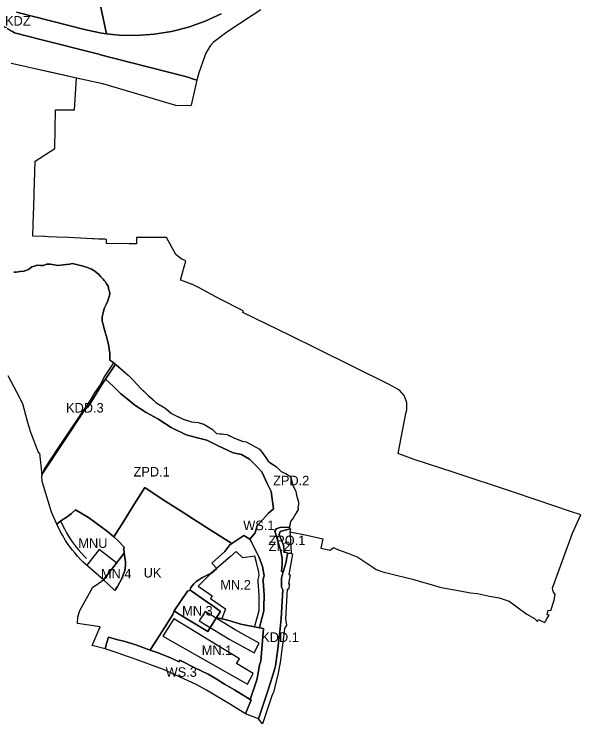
# Model space of a CAD drawing. Extents: x 7422965 to 7424741, y 5551047 to 5553849.
# Drawn here: x 7424029 to 7424741, y 5551047 to 5551939 of the extents above; entities that cross this region are included whole.
import ezdxf

# ---------------------------------------------------------------- set-up
doc = ezdxf.new("R2010")
doc.units = 0
for name, color, linetype in [('LIN_Linia Zabudowy Nieprzekraczalna', 7, 'Continuous'), ('linie_rozgraniczajace', 7, 'Continuous'), ('oznaczenia_przeznaczen', 7, 'Continuous'), ('Tereny dla których obowiązuje MPZP LInia tramwajowa_', 7, 'Continuous'), ('Tereny dla których obowiązuje MPZP_SIEWNA_', 7, 'Continuous')]:
    doc.layers.add(name, color=color, linetype=linetype)

msp = doc.modelspace()

# ---------------------------------------------------------------- linework, layer by layer
at = {"layer": 'LIN_Linia Zabudowy Nieprzekraczalna'}
for points in [[(7424086.9, 5551302.23), (7424091.81, 5551292.33), (7424094.5, 5551287.54), (7424098.23, 5551281.11), (7424101.45, 5551276.33), (7424102.69, 5551274.63), (7424106.51, 5551269.64), (7424109.66, 5551265.92), (7424112.87, 5551262.27), (7424116.93, 5551257.71), (7424119.41, 5551255.39)], [(7424157.46, 5551249.4), (7424135.64, 5551266.43), (7424120.13, 5551246.75)], [(7424330.98, 5551169.62), (7424331.53, 5551171.74), (7424336.3, 5551190.07), (7424336.37, 5551194.34), (7424336.6, 5551209.2), (7424335.4, 5551226.04), (7424335.03, 5551228.64), (7424336.65, 5551233.69), (7424335.86, 5551237.95), (7424335.86, 5551237.95), (7424332.94, 5551250.04), (7424331.02, 5551258.06), (7424316.07, 5551256.25), (7424307.51, 5551264.16), (7424300.57, 5551257.64), (7424276.18, 5551236.6), (7424259.68, 5551220.57), (7424273.33, 5551211.16), (7424277.51, 5551208.28), (7424275.25, 5551204.98), (7424294.21, 5551191.91), (7424289.71, 5551179.29)], [(7424261.26, 5551176.82), (7424299.42, 5551153.27), (7424330.27, 5551136.45), (7424336.49, 5551149.01), (7424306.45, 5551165.38), (7424268.81, 5551188.62), (7424261.26, 5551176.82)], [(7424229.09, 5551179.23), (7424221.21, 5551166.77), (7424215.27, 5551157.4), (7424321.63, 5551097.36), (7424329.04, 5551110.48), (7424308.15, 5551123.21), (7424311.69, 5551129.27), (7424229.09, 5551179.23)]]:
    msp.add_lwpolyline(points, dxfattribs=at)
at = {"layer": 'linie_rozgraniczajace'}
for points in [[(7424120.1, 5552030.52), (7424144.75, 5551914.84), (7424138.51, 5551915.55), (7424134.69, 5551916.34), (7424116.88, 5551920.02), (7424031.65, 5551941.72)], [(7424288.66, 5551939.77), (7424268.6, 5551930.5), (7424247.79, 5551923.1), (7424226.39, 5551917.62), (7424204.58, 5551914.1), (7424182.55, 5551912.57), (7424160.46, 5551913.06), (7424144.75, 5551914.84), (7424120.1, 5552030.52)], [(7424338.43, 5551944.9), (7424327.49, 5551937.52), (7424295.81, 5551916.92), (7424278.65, 5551903.92), (7424275.17, 5551900.11), (7424272.19, 5551895.33), (7424269.35, 5551890.42), (7424267.75, 5551885.84), (7424260.49, 5551865.76), (7424258.29, 5551856.52), (7424253.82, 5551857.89), (7424248.24, 5551859.6), (7424244.12, 5551860.87), (7424153.41, 5551884.24), (7424137.07, 5551888.39), (7424134.98, 5551888.92), (7424060.02, 5551907.95), (7424029.29, 5551915.75), (7424026.49, 5551917.43), (7424025.86, 5551917.8), (7424023.81, 5551919.03), (7424016.3, 5551923.51), (7424014.01, 5551923.99), (7423937.85, 5551940.09)], [(7424031.65, 5551941.72), (7424116.88, 5551920.02), (7424134.69, 5551916.34), (7424138.51, 5551915.55), (7424144.75, 5551914.84), (7424160.46, 5551913.06), (7424182.55, 5551912.57), (7424204.58, 5551914.1), (7424226.39, 5551917.62), (7424247.79, 5551923.1), (7424268.6, 5551930.5), (7424288.66, 5551939.77)], [(7424026.49, 5551917.43), (7424029.29, 5551915.75), (7424060.02, 5551907.95), (7424134.98, 5551888.92), (7424137.07, 5551888.39), (7424153.41, 5551884.24), (7424244.12, 5551860.87), (7424248.24, 5551859.6), (7424253.82, 5551857.89), (7424258.29, 5551856.52), (7424251.03, 5551825.07), (7424250.65, 5551824.29), (7424231.82, 5551824.48), (7424207.95, 5551831.54), (7424195.27, 5551835.29), (7424139.86, 5551851.68), (7424106.89, 5551859.08), (7424053.04, 5551871.18), (7424030.65, 5551876.21), (7424024.75, 5551877.53)], [(7424143.23, 5551480.6), (7424155.85, 5551499.51), (7424157.31, 5551498.25), (7424171.99, 5551485.61), (7424177.75, 5551479.64), (7424187.73, 5551468.97), (7424196.98, 5551460.22), (7424206.73, 5551451.46), (7424217.86, 5551444.5), (7424226.44, 5551437.58), (7424240.98, 5551430.18), (7424251.49, 5551427.06), (7424260, 5551426.11), (7424266.96, 5551424.11), (7424277.5, 5551417.67), (7424283.07, 5551412.39), (7424295.73, 5551411.05), (7424305.5, 5551406.56), (7424314.91, 5551402.72), (7424320.18, 5551401.96), (7424337.02, 5551392.72), (7424341.56, 5551386.77), (7424347.82, 5551377.72), (7424358.13, 5551370.24), (7424364.03, 5551364.43), (7424370.78, 5551361.67), (7424374.13, 5551359.25), (7424376.35, 5551356.96), (7424378.82, 5551347.56), (7424382.34, 5551339.53), (7424383.41, 5551334.98), (7424385.78, 5551325.96), (7424385.87, 5551323.15), (7424384.98, 5551319.4), (7424385.56, 5551316.43), (7424382.32, 5551311.88), (7424379.31, 5551306.11), (7424375.8, 5551301.77), (7424374.36, 5551294.1), (7424363.6, 5551294.44), (7424357.85, 5551292.65), (7424356.12, 5551290.17), (7424363.48, 5551263.88), (7424365.2, 5551255.51), (7424365.15, 5551247.64), (7424364.38, 5551239.28), (7424366.46, 5551238.11), (7424366.18, 5551237.18), (7424364.59, 5551230.51), (7424364.65, 5551219.27), (7424366.13, 5551215.73), (7424364.17, 5551179.85), (7424362.34, 5551162.92), (7424361.57, 5551156.29), (7424359.46, 5551138.15), (7424357.05, 5551120.18), (7424356.21, 5551116.93), (7424348.01, 5551091.33), (7424337.23, 5551058.6), (7424335.59, 5551053.83), (7424319.2, 5551060.14), (7424326.52, 5551077.56), (7424325.23, 5551078.01), (7424333.66, 5551102.68), (7424335.57, 5551113.64), (7424336.92, 5551121.42), (7424338.63, 5551126.39), (7424341.72, 5551167.4), (7424336.79, 5551168.12), (7424337.34, 5551170.24), (7424342.29, 5551189.25), (7424342.37, 5551194.25), (7424342.6, 5551209.37), (7424341.37, 5551226.68), (7424341.16, 5551228.13), (7424342.82, 5551233.3), (7424340.59, 5551245.37), (7424336.61, 5551256.54), (7424326.75, 5551275.64), (7424324.81, 5551279.65), (7424331.32, 5551287.68), (7424333.79, 5551296.85), (7424341.17, 5551304.1), (7424347.86, 5551311.59), (7424354.51, 5551317.54), (7424351.48, 5551339.44), (7424347.01, 5551348.51), (7424339.81, 5551364.05), (7424334.3, 5551370.11), (7424324.5, 5551380.1), (7424314.3, 5551386.03), (7424303.96, 5551388.02), (7424284.75, 5551396.63), (7424270.57, 5551403.88), (7424257.14, 5551407.32), (7424244.6, 5551410.84), (7424225.93, 5551420.07), (7424209.06, 5551430.88), (7424194.67, 5551438.74), (7424180.28, 5551447.97)], [(7424180.28, 5551447.97), (7424170.73, 5551456.04), (7424162.45, 5551462.64), (7424153.22, 5551472.01), (7424143.23, 5551480.6)]]:
    msp.add_lwpolyline(points, dxfattribs=at)
for points in [[(7424124.74, 5551454.39), (7424130.04, 5551463.54), (7424137.23, 5551473.52), (7424141.16, 5551482.38), (7424153.93, 5551501.16), (7424155.85, 5551499.51), (7424143.23, 5551480.6), (7424138.31, 5551473.24), (7424125.01, 5551451.39), (7424120.96, 5551444.98), (7424115.51, 5551439.09), (7424064.92, 5551363.3), (7424066.24, 5551366.98), (7424084.66, 5551395.09)], [(7424063.81, 5551352.05), (7424063.59, 5551359.61), (7424064.92, 5551363.3), (7424115.51, 5551439.09), (7424120.96, 5551444.98), (7424125.01, 5551451.39), (7424138.31, 5551473.24), (7424143.23, 5551480.6), (7424153.22, 5551472.01), (7424162.45, 5551462.64), (7424170.73, 5551456.04), (7424180.28, 5551447.97), (7424194.67, 5551438.74), (7424209.06, 5551430.88), (7424225.93, 5551420.07), (7424244.6, 5551410.84), (7424257.14, 5551407.32), (7424270.57, 5551403.88), (7424284.75, 5551396.63), (7424303.96, 5551388.02), (7424314.3, 5551386.03), (7424324.5, 5551380.1), (7424334.3, 5551370.11), (7424339.81, 5551364.05), (7424347.01, 5551348.51), (7424351.48, 5551339.44), (7424354.51, 5551317.54), (7424347.86, 5551311.59), (7424341.17, 5551304.1), (7424333.79, 5551296.85), (7424331.32, 5551287.68), (7424324.81, 5551279.65), (7424317.22, 5551284.03), (7424302, 5551273.99), (7424273.44, 5551291.96), (7424254.09, 5551304.61), (7424243.01, 5551311.61), (7424214.43, 5551329.89), (7424192.62, 5551344.53), (7424176.77, 5551319.22), (7424166.29, 5551302.13), (7424153.78, 5551282.48), (7424145.93, 5551289.26), (7424121.93, 5551306.93), (7424105.93, 5551316.57), (7424100.6, 5551311.67), (7424095.35, 5551307.77), (7424087.29, 5551302.56), (7424082.19, 5551298.22), (7424075.6, 5551313.66), (7424067.23, 5551341.02)], [(7424108.4, 5551173.57), (7424108.85, 5551181.96), (7424111.2, 5551189.9), (7424127.5, 5551219.28), (7424133.39, 5551223.17), (7424135.03, 5551224.25), (7424140.96, 5551228.43), (7424146.99, 5551222.5), (7424154.99, 5551214.81), (7424158.64, 5551220.18), (7424164.46, 5551230.92), (7424165.73, 5551234.56), (7424167.66, 5551240.29), (7424168.43, 5551246.47), (7424168.38, 5551251.18), (7424167.01, 5551262.06), (7424166.37, 5551268.4), (7424167.01, 5551269.61), (7424159.4, 5551277.62), (7424153.78, 5551282.48), (7424166.29, 5551302.13), (7424176.77, 5551319.22), (7424192.62, 5551344.53), (7424214.43, 5551329.89), (7424243.01, 5551311.61), (7424254.09, 5551304.61), (7424273.44, 5551291.96), (7424302, 5551273.99), (7424299.53, 5551272.36), (7424293.13, 5551264.22), (7424277.15, 5551249.25), (7424283.26, 5551242.71), (7424276.39, 5551236.78), (7424276.33, 5551236.82), (7424271.8, 5551234.8), (7424264.59, 5551230.81), (7424260.86, 5551228.6), (7424257.41, 5551226.11), (7424254.38, 5551223.21), (7424250.69, 5551218.83), (7424249.64, 5551215.27), (7424246.6, 5551214.27), (7424229.47, 5551189.25), (7424227.92, 5551184.85), (7424217.83, 5551168.91), (7424200.84, 5551142.11), (7424199.56, 5551140.09), (7424181.43, 5551146.56), (7424176.25, 5551148.21), (7424166.25, 5551151.39), (7424158.75, 5551152.93), (7424147.08, 5551156.15), (7424145.22, 5551149.6), (7424142.89, 5551141.64), (7424126.47, 5551145.67), (7424136.85, 5551169.19)], [(7424082.19, 5551298.22), (7424087.29, 5551302.56), (7424095.35, 5551307.77), (7424100.6, 5551311.67), (7424105.93, 5551316.57), (7424121.93, 5551306.93), (7424145.93, 5551289.26), (7424153.78, 5551282.48), (7424159.4, 5551277.62), (7424167.01, 5551269.61), (7424166.37, 5551268.4), (7424167.01, 5551262.06), (7424140.96, 5551228.43), (7424115.54, 5551250.79), (7424112.63, 5551253.52), (7424108.38, 5551258.29), (7424105.12, 5551262), (7424101.84, 5551265.87), (7424097.89, 5551271.04), (7424096.54, 5551272.88), (7424093.14, 5551277.93), (7424089.29, 5551284.57), (7424086.51, 5551289.53)], [(7424356.12, 5551290.17), (7424357.85, 5551292.65), (7424363.6, 5551294.44), (7424374.36, 5551294.1), (7424375.54, 5551292.71), (7424362.82, 5551289.28), (7424361.5, 5551285.28), (7424367.06, 5551271.81), (7424368.05, 5551265.17), (7424367.6, 5551263.36), (7424369.19, 5551263.16), (7424372.38, 5551261.97), (7424371.38, 5551256.73), (7424370.31, 5551251.21), (7424366.46, 5551238.11), (7424364.38, 5551239.28), (7424365.15, 5551247.64), (7424365.2, 5551255.51), (7424363.48, 5551263.88)], [(7424361.5, 5551285.28), (7424362.82, 5551289.28), (7424375.54, 5551292.71), (7424376, 5551292.16), (7424375.16, 5551288.57), (7424375.24, 5551284.28), (7424376.17, 5551270.45), (7424376.66, 5551261.51), (7424372.38, 5551261.97), (7424369.19, 5551263.16), (7424367.6, 5551263.36), (7424368.05, 5551265.17), (7424367.06, 5551271.81)], [(7424249.64, 5551215.27), (7424250.69, 5551218.83), (7424254.38, 5551223.21), (7424257.41, 5551226.11), (7424260.86, 5551228.6), (7424264.59, 5551230.81), (7424271.8, 5551234.8), (7424276.33, 5551236.82), (7424276.39, 5551236.78), (7424283.26, 5551242.71), (7424277.15, 5551249.25), (7424293.13, 5551264.22), (7424299.53, 5551272.36), (7424302, 5551273.99), (7424317.22, 5551284.03), (7424324.81, 5551279.65), (7424326.75, 5551275.64), (7424336.61, 5551256.54), (7424340.59, 5551245.37), (7424342.82, 5551233.3), (7424341.16, 5551228.13), (7424341.37, 5551226.68), (7424342.6, 5551209.37), (7424342.37, 5551194.25), (7424342.29, 5551189.25), (7424337.34, 5551170.24), (7424336.79, 5551168.12), (7424313.32, 5551172.78), (7424298.3, 5551177.24), (7424282.88, 5551180.93), (7424287.88, 5551188.73), (7424279.52, 5551194.75), (7424267.66, 5551202.93), (7424252.18, 5551213.6)], [(7424140.96, 5551228.43), (7424167.01, 5551262.06), (7424168.38, 5551251.18), (7424168.43, 5551246.47), (7424167.66, 5551240.29), (7424165.73, 5551234.56), (7424164.46, 5551230.92), (7424158.64, 5551220.18), (7424154.99, 5551214.81), (7424146.99, 5551222.5)], [(7424335.59, 5551053.83), (7424337.23, 5551058.6), (7424348.01, 5551091.33), (7424356.21, 5551116.93), (7424357.05, 5551120.18), (7424359.46, 5551138.15), (7424361.57, 5551156.29), (7424362.34, 5551162.92), (7424364.17, 5551179.85), (7424366.13, 5551215.73), (7424364.65, 5551219.27), (7424364.59, 5551230.51), (7424366.18, 5551237.18), (7424366.46, 5551238.11), (7424370.31, 5551251.21), (7424371.38, 5551256.73), (7424372.38, 5551261.97), (7424376.66, 5551261.51), (7424378.52, 5551261.17), (7424377.15, 5551253.37), (7424373.9, 5551234.92), (7424375.57, 5551234.85), (7424373.46, 5551223.56), (7424374.37, 5551223.42), (7424373.11, 5551216.46), (7424371.84, 5551216.57), (7424369.75, 5551179.4), (7424370.9, 5551171.42), (7424368.46, 5551167.29), (7424366.54, 5551153.17), (7424366.05, 5551149.6), (7424364.55, 5551137.84), (7424363.16, 5551126.98), (7424360.42, 5551111.07), (7424356.61, 5551095.74), (7424354.42, 5551086.89), (7424352.87, 5551083.67), (7424348.16, 5551070.19), (7424345.53, 5551062.39), (7424340.51, 5551047.45)], [(7424229.47, 5551189.25), (7424246.6, 5551214.27), (7424249.64, 5551215.27), (7424252.18, 5551213.6), (7424267.66, 5551202.93), (7424279.52, 5551194.75), (7424287.88, 5551188.73), (7424282.88, 5551180.93), (7424273.08, 5551165.36), (7424271.78, 5551163.28), (7424271.78, 5551163.28), (7424249.78, 5551176.86), (7424245.52, 5551179.49), (7424233.78, 5551186.71)], [(7424199.56, 5551140.09), (7424200.84, 5551142.11), (7424217.83, 5551168.91), (7424227.92, 5551184.85), (7424229.47, 5551189.25), (7424233.78, 5551186.71), (7424245.52, 5551179.49), (7424249.78, 5551176.86), (7424271.78, 5551163.28), (7424271.78, 5551163.28), (7424273.08, 5551165.36), (7424282.88, 5551180.93), (7424298.3, 5551177.24), (7424313.32, 5551172.78), (7424336.79, 5551168.12), (7424341.72, 5551167.4), (7424338.63, 5551126.39), (7424336.92, 5551121.42), (7424335.57, 5551113.64), (7424333.66, 5551102.68), (7424325.23, 5551078.01), (7424305.35, 5551090.05), (7424293.12, 5551097.46), (7424282.25, 5551103.92), (7424272.21, 5551109.65), (7424255.78, 5551117.87), (7424239.16, 5551126.18), (7424236.69, 5551127.35), (7424236.01, 5551125.51), (7424224.27, 5551130.63), (7424214.69, 5551134.7), (7424209.77, 5551136.45), (7424209.77, 5551136.45), (7424203.37, 5551138.73)], [(7424142.89, 5551141.64), (7424145.22, 5551149.6), (7424147.08, 5551156.15), (7424158.75, 5551152.93), (7424166.25, 5551151.39), (7424176.25, 5551148.21), (7424181.43, 5551146.56), (7424199.56, 5551140.09), (7424203.37, 5551138.73), (7424209.77, 5551136.45), (7424209.77, 5551136.45), (7424214.69, 5551134.7), (7424224.27, 5551130.63), (7424236.01, 5551125.51), (7424236.69, 5551127.35), (7424239.16, 5551126.18), (7424255.78, 5551117.87), (7424272.21, 5551109.65), (7424282.25, 5551103.92), (7424293.12, 5551097.46), (7424305.35, 5551090.05), (7424325.23, 5551078.01), (7424326.52, 5551077.56), (7424319.2, 5551060.14), (7424300.48, 5551071.55), (7424270.45, 5551089.59), (7424257.26, 5551096.74), (7424216.48, 5551115.69), (7424177.17, 5551129.81), (7424169.61, 5551132.45), (7424159.16, 5551136.29)]]:
    msp.add_lwpolyline(points, close=True, dxfattribs=at)
at = {"layer": 'Tereny dla których obowiązuje MPZP LInia tramwajowa_'}
msp.add_lwpolyline([(7424020.78, 5551485.05), (7424032.02, 5551463.8), (7424039.06, 5551449.86), (7424044.59, 5551429.51), (7424046.99, 5551420.68), (7424049.05, 5551414.16), (7424058.81, 5551389.06), (7424060.38, 5551387.44), (7424063.54, 5551360), (7424063.75, 5551360.07), (7424066.24, 5551366.98), (7424072.13, 5551375.97), (7424084.66, 5551395.09), (7424109.01, 5551431.12), (7424124.74, 5551454.4), (7424127.94, 5551459.92), (7424130.04, 5551463.54), (7424137.23, 5551473.52), (7424141.16, 5551482.38), (7424153.93, 5551501.16), (7424151.41, 5551502.84), (7424148.89, 5551504.51), (7424148.8, 5551509.18), (7424148.71, 5551513.84), (7424148.08, 5551517.97), (7424147.45, 5551522.09), (7424146.25, 5551527.42), (7424145.04, 5551532.75), (7424142.3, 5551542.51), (7424139.56, 5551552.26), (7424139.37, 5551552.93), (7424139.21, 5551555.95), (7424139.05, 5551558.97), (7424139.94, 5551562.32), (7424140.82, 5551565.66), (7424141.79, 5551569.52), (7424144.06, 5551574.36), (7424146.32, 5551579.19), (7424147.67, 5551583.34), (7424149.01, 5551587.49), (7424148.89, 5551588.06), (7424148.76, 5551588.63), (7424148.03, 5551591.88), (7424147.77, 5551593.03), (7424146.78, 5551597.42), (7424144.8, 5551600.31), (7424142.81, 5551603.19), (7424141.69, 5551604.72), (7424140.57, 5551606.24), (7424137.62, 5551609.4), (7424134.66, 5551612.55), (7424132.42, 5551614.38), (7424130.17, 5551616.21), (7424128.03, 5551617.51), (7424125.89, 5551618.81), (7424120.62, 5551620.81), (7424117.94, 5551621.74), (7424115.26, 5551622.66), (7424108.56, 5551624.34), (7424101.86, 5551626.02), (7424098.07, 5551625.36), (7424090.71, 5551624.36), (7424083.34, 5551623.36), (7424078.85, 5551624.34), (7424074.36, 5551625.32), (7424069.14, 5551625), (7424065.57, 5551623.29), (7424061.62, 5551623.51), (7424057.66, 5551623.73), (7424054.32, 5551622.76), (7424050.97, 5551621.79), (7424050.78, 5551621.64), (7424048.8, 5551620), (7424046.81, 5551618.36), (7424044.07, 5551617.42), (7424041.32, 5551616.48), (7424036.16, 5551615.8), (7424030.99, 5551615.11), (7424028.39, 5551614.97)], dxfattribs=at)
at = {"layer": 'Tereny dla których obowiązuje MPZP_SIEWNA_'}
for points in [[(7424066.6, 5551659.87), (7424052.04, 5551660.53), (7424052.95, 5551688.85), (7424053.18, 5551695.89), (7424053.75, 5551713.85), (7424055.07, 5551754.73), (7424079.6, 5551770.54), (7424080.45, 5551819.16), (7424104.47, 5551819.18), (7424106.89, 5551859.08), (7424079.97, 5551865.13), (7424053.04, 5551871.18), (7424034.51, 5551875.34), (7424024.94, 5551877.49)], [(7424028.39, 5551614.97), (7424030.99, 5551615.11), (7424036.16, 5551615.8), (7424041.32, 5551616.48), (7424044.07, 5551617.42), (7424046.81, 5551618.36), (7424048.8, 5551620), (7424050.78, 5551621.64), (7424050.97, 5551621.79), (7424054.32, 5551622.76), (7424057.66, 5551623.73), (7424061.62, 5551623.51), (7424065.57, 5551623.29), (7424069.14, 5551625), (7424074.36, 5551625.32), (7424078.85, 5551624.34), (7424083.34, 5551623.36), (7424090.71, 5551624.36), (7424098.07, 5551625.36), (7424101.86, 5551626.02), (7424108.56, 5551624.34), (7424115.26, 5551622.66), (7424117.94, 5551621.74), (7424120.62, 5551620.81), (7424125.89, 5551618.81), (7424128.03, 5551617.51), (7424130.17, 5551616.21), (7424132.42, 5551614.38), (7424134.66, 5551612.55), (7424137.62, 5551609.4), (7424140.57, 5551606.24), (7424141.69, 5551604.72), (7424142.81, 5551603.19), (7424144.8, 5551600.31), (7424146.78, 5551597.42), (7424147.77, 5551593.03), (7424148.03, 5551591.88), (7424148.76, 5551588.63), (7424148.89, 5551588.06), (7424149.01, 5551587.49), (7424147.67, 5551583.34), (7424146.32, 5551579.19), (7424144.06, 5551574.36), (7424141.79, 5551569.52), (7424140.82, 5551565.66), (7424139.94, 5551562.32), (7424139.05, 5551558.97), (7424139.21, 5551555.95), (7424139.37, 5551552.93), (7424139.56, 5551552.26), (7424142.3, 5551542.51), (7424145.04, 5551532.75), (7424146.25, 5551527.42), (7424147.45, 5551522.09), (7424148.08, 5551517.97), (7424148.71, 5551513.84), (7424148.8, 5551509.18), (7424148.89, 5551504.51), (7424151.41, 5551502.84), (7424153.93, 5551501.16), (7424155.62, 5551499.71), (7424157.31, 5551498.25), (7424157.49, 5551498.09), (7424171.99, 5551485.62), (7424174.87, 5551482.63), (7424177.75, 5551479.64), (7424182.74, 5551474.31), (7424187.73, 5551468.97), (7424192.36, 5551464.6), (7424196.98, 5551460.22), (7424201.86, 5551455.84), (7424206.73, 5551451.46), (7424212.3, 5551447.98), (7424217.86, 5551444.5), (7424222.15, 5551441.04), (7424226.44, 5551437.58), (7424233.71, 5551433.88), (7424240.98, 5551430.18), (7424246.24, 5551428.62), (7424251.49, 5551427.06), (7424255.75, 5551426.59), (7424260, 5551426.11), (7424263.48, 5551425.11), (7424266.96, 5551424.11), (7424272.23, 5551420.89), (7424277.5, 5551417.67), (7424280.29, 5551415.03), (7424283.07, 5551412.39), (7424289.4, 5551411.72), (7424295.73, 5551411.05), (7424300.62, 5551408.81), (7424305.5, 5551406.56), (7424310.21, 5551404.64), (7424314.91, 5551402.72), (7424317.55, 5551402.34), (7424320.18, 5551401.96), (7424328.6, 5551397.34), (7424337.02, 5551392.72), (7424339.29, 5551389.74), (7424341.56, 5551386.77), (7424344.69, 5551382.24), (7424347.82, 5551377.72), (7424352.98, 5551373.98), (7424358.13, 5551370.24), (7424361.08, 5551367.34), (7424364.03, 5551364.43), (7424367.41, 5551363.05), (7424370.78, 5551361.67), (7424372.46, 5551360.46), (7424374.13, 5551359.25), (7424375.24, 5551358.11), (7424376.35, 5551356.96), (7424377.59, 5551352.26), (7424378.82, 5551347.56), (7424380.58, 5551343.55), (7424382.34, 5551339.53), (7424383.41, 5551334.98), (7424384.6, 5551330.47), (7424385.78, 5551325.96), (7424385.83, 5551324.56), (7424385.87, 5551323.15), (7424385.43, 5551321.28), (7424384.98, 5551319.4), (7424385.27, 5551317.91), (7424385.56, 5551316.43), (7424383.94, 5551314.15), (7424382.32, 5551311.88), (7424380.82, 5551308.99), (7424379.31, 5551306.11), (7424377.56, 5551303.94), (7424375.8, 5551301.77), (7424375.08, 5551297.94), (7424374.36, 5551294.1), (7424375.18, 5551293.13), (7424376, 5551292.16), (7424375.58, 5551290.37), (7424375.16, 5551288.57), (7424396.29, 5551284.57), (7424416.31, 5551279.91), (7424414.07, 5551268.38), (7424425.86, 5551265.81), (7424429.81, 5551268.91), (7424433.94, 5551267.16), (7424440.77, 5551264.58), (7424447.94, 5551261.94), (7424460.29, 5551256.83), (7424480.49, 5551243.58), (7424483.61, 5551241.54), (7424493.02, 5551238), (7424498.53, 5551236.63), (7424528.96, 5551229.05), (7424543.47, 5551224.94), (7424549.65, 5551223.18), (7424563.57, 5551219.34), (7424567.44, 5551218.27), (7424591.08, 5551214), (7424602, 5551212.25), (7424610.57, 5551211.07), (7424618.35, 5551209.35), (7424625.73, 5551208.04), (7424638.13, 5551205.85), (7424650.49, 5551201.6), (7424656.98, 5551197.04), (7424663.54, 5551192.03), (7424672.55, 5551185.14), (7424682.2, 5551179.63), (7424686.18, 5551175.97), (7424687.35, 5551178.36), (7424693.34, 5551175.76), (7424695.24, 5551174.92), (7424696.05, 5551176.28), (7424698.32, 5551180.11), (7424700.67, 5551184.05), (7424698.45, 5551184.54), (7424699.62, 5551190.48), (7424702.77, 5551189.91), (7424707.17, 5551202.73), (7424708.21, 5551209.94), (7424706.19, 5551212.84), (7424705.34, 5551215.39), (7424705.06, 5551217.76), (7424705.77, 5551220.64), (7424729.91, 5551286.92), (7424740.52, 5551310.12), (7424727.54, 5551314.47), (7424685.74, 5551328.44), (7424653.3, 5551339.29), (7424581.47, 5551363.31), (7424549.05, 5551373.86), (7424531.05, 5551379.72), (7424512.1, 5551386.87), (7424510.89, 5551387.32), (7424520.89, 5551437.29), (7424521.86, 5551442.1), (7424522.1, 5551451.24), (7424519.97, 5551456.82), (7424518.75, 5551460.02), (7424512.74, 5551466.95), (7424498.85, 5551474.31), (7424454.25, 5551496.64), (7424409.42, 5551518.6), (7424376.14, 5551535.26), (7424315.95, 5551564.31), (7424316.19, 5551565.66), (7424316.32, 5551566.38), (7424287.38, 5551581.34), (7424260.97, 5551595.32), (7424253.43, 5551599.31), (7424241.32, 5551603.73), (7424237.95, 5551604.95), (7424237.56, 5551605.1), (7424240.19, 5551614.48), (7424244.37, 5551629.4), (7424238.48, 5551632.05), (7424231.61, 5551637.43), (7424219.97, 5551658.78), (7424199.51, 5551658.79), (7424182.23, 5551658.81), (7424182.22, 5551650.9), (7424182.06, 5551650.9), (7424182.05, 5551650.8), (7424173.32, 5551650.92), (7424145.24, 5551651.27), (7424144.6, 5551651.28), (7424144.77, 5551655.61), (7424144.8, 5551656.34), (7424142.43, 5551656.45), (7424134.81, 5551656.79), (7424128.71, 5551657.07), (7424126.96, 5551657.15), (7424111.98, 5551657.82), (7424097, 5551658.5), (7424082.01, 5551659.17), (7424071.52, 5551659.64), (7424067.03, 5551659.84), (7424066.6, 5551659.87)]]:
    msp.add_lwpolyline(points, dxfattribs=at)

# ---------------------------------------------------------------- texts
at = {"layer": 'oznaczenia_przeznaczen'}
for s, p in [('KDZ', (7424017.2, 5551924.99)), ('KDD.3', (7424093.88, 5551438.64)), ('ZPD.1', (7424178.64, 5551358.27)), ('ZPD.2', (7424353.96, 5551347.21)), ('WS.1', (7424316.45, 5551290.85)), ('MNU', (7424109.3, 5551268.55)), ('ZPO.1', (7424348.08, 5551272.01)), ('ZI.2', (7424348.36, 5551264.48)), ('MN.4', (7424137.72, 5551230.11)), ('UK', (7424191.35, 5551231.34)), ('MN.2', (7424287.66, 5551216.14)), ('MN.3', (7424239.65, 5551183.58)), ('KDD.1', (7424339.04, 5551150.29)), ('MN.1', (7424264.31, 5551133.92)), ('WS.3', (7424218.95, 5551106.52))]:
    msp.add_text(s, height=12, dxfattribs=at).set_placement(p)

doc.saveas('drawing.dxf')
